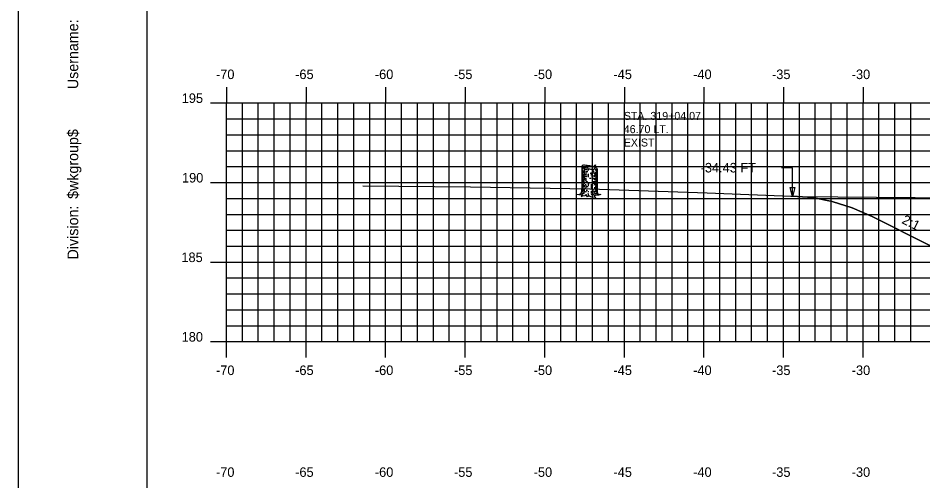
# Model space of a CAD drawing. Extents: x 1139428 to 1139598, y 608981 to 609091.
# Drawn here: x 1139428.4 to 1139485.2, y 609011.6 to 609040.7 of the extents above; entities that cross this region are included whole.
import ezdxf

# ---------------------------------------------------------------- set-up
doc = ezdxf.new("R2010")
doc.units = 0
for name, color, linetype in [('ANNOTATION', 7, 'Continuous'), ('BORDER', 7, 'Continuous'), ('D_Roadway_SlopeLines', 7, 'Continuous'), ('D_Text_Monospaced', 7, 'Continuous'), ('D_Text_Standard', 7, 'Continuous'), ('H_V ANNOTATION', 7, 'Continuous'), ('MAJOR', 7, 'Continuous'), ('MINOR', 7, 'Continuous'), ('PLOT BOUNDARY', 7, 'Continuous'), ('S_Roadway_Centerline', 7, 'Continuous'), ('S_Trees_Decid_NonPay', 7, 'Continuous')]:
    doc.layers.add(name, color=color, linetype=linetype)

msp = doc.modelspace()

# ---------------------------------------------------------------- linework, layer by layer
msp.add_lwpolyline([(1139477.03, 609029.476), (1139478.28, 609029.383), (1139479.53, 609029.138), (1139480.78, 609028.741), (1139482.03, 609028.192), (1139485.737, 609026.338), (1139488.737, 609027.338), (1139496.461, 609029.913), (1139496.462, 609029.913), (1139500.462, 609030.073), (1139511.462, 609030.293), (1139522.462, 609030.073), (1139526.462, 609029.913), (1139534.185, 609027.338), (1139537.185, 609026.338), (1139537.772, 609026.632), (1139539.022, 609027.171), (1139540.272, 609027.537), (1139541.522, 609027.732), (1139542.772, 609027.754)])
at = {"layer": 'BORDER'}
msp.add_lwpolyline([(1139436.462, 608984.335), (1139596.462, 608984.335), (1139596.462, 609089.335), (1139436.462, 609089.335)], close=True, dxfattribs=at)
at = {"layer": 'D_Roadway_SlopeLines'}
msp.add_lwpolyline([(1139485.737, 609026.338), (1139482.03, 609028.192), (1139480.78, 609028.741), (1139479.53, 609029.138), (1139478.28, 609029.383), (1139477.03, 609029.476)], dxfattribs=at)
at = {"layer": 'D_Text_Standard'}
msp.add_lwpolyline([(1139477.03, 609029.442), (1139477.027, 609031.267), (1139476.347, 609031.267)], dxfattribs=at)
msp.add_lwpolyline([(1139477.03, 609029.442), (1139476.884, 609030.024), (1139477.175, 609030.024)], close=True, dxfattribs=at)
at = {"layer": 'MAJOR'}
for p, q in [((1139441.462, 609036.337), (1139441.462, 609035.335)), ((1139446.462, 609036.337), (1139446.462, 609035.335)), ((1139451.462, 609036.337), (1139451.462, 609035.335)), ((1139456.462, 609036.337), (1139456.462, 609035.335)), ((1139461.462, 609036.337), (1139461.462, 609035.335)), ((1139466.462, 609036.337), (1139466.462, 609035.335)), ((1139471.462, 609036.337), (1139471.462, 609035.335)), ((1139476.462, 609036.337), (1139476.462, 609035.335)), ((1139481.462, 609036.337), (1139481.462, 609035.335)), ((1139440.46, 609035.335), (1139441.462, 609035.335)), ((1139441.462, 609035.335), (1139581.462, 609035.335)), ((1139441.462, 609020.335), (1139441.462, 609035.335)), ((1139441.462, 609020.335), (1139441.462, 609035.335)), ((1139441.462, 609035.335), (1139581.462, 609035.335)), ((1139446.462, 609020.335), (1139446.462, 609035.335)), ((1139451.462, 609020.335), (1139451.462, 609035.335)), ((1139456.462, 609020.335), (1139456.462, 609035.335)), ((1139461.462, 609020.335), (1139461.462, 609035.335)), ((1139466.462, 609020.335), (1139466.462, 609035.335)), ((1139471.462, 609020.335), (1139471.462, 609035.335)), ((1139476.462, 609020.335), (1139476.462, 609035.335)), ((1139481.462, 609020.335), (1139481.462, 609035.335)), ((1139440.46, 609030.335), (1139441.462, 609030.335)), ((1139441.462, 609030.335), (1139581.462, 609030.335)), ((1139440.46, 609025.335), (1139441.462, 609025.335)), ((1139441.462, 609025.335), (1139581.462, 609025.335)), ((1139440.46, 609020.335), (1139441.462, 609020.335)), ((1139441.462, 609020.335), (1139581.462, 609020.335)), ((1139441.462, 609020.335), (1139581.462, 609020.335)), ((1139441.462, 609019.333), (1139441.462, 609020.335)), ((1139446.462, 609019.333), (1139446.462, 609020.335)), ((1139451.462, 609019.333), (1139451.462, 609020.335)), ((1139456.462, 609019.333), (1139456.462, 609020.335)), ((1139461.462, 609019.333), (1139461.462, 609020.335)), ((1139466.462, 609019.333), (1139466.462, 609020.335)), ((1139471.462, 609019.333), (1139471.462, 609020.335)), ((1139476.462, 609019.333), (1139476.462, 609020.335)), ((1139481.462, 609019.333), (1139481.462, 609020.335))]:
    msp.add_line(p, q, dxfattribs=at)
at = {"layer": 'MINOR'}
for p, q in [((1139442.462, 609020.335), (1139442.462, 609035.335)), ((1139443.462, 609020.335), (1139443.462, 609035.335)), ((1139444.462, 609020.335), (1139444.462, 609035.335)), ((1139445.462, 609020.335), (1139445.462, 609035.335)), ((1139447.462, 609020.335), (1139447.462, 609035.335)), ((1139448.462, 609020.335), (1139448.462, 609035.335)), ((1139449.462, 609020.335), (1139449.462, 609035.335)), ((1139450.462, 609020.335), (1139450.462, 609035.335)), ((1139452.462, 609020.335), (1139452.462, 609035.335)), ((1139453.462, 609020.335), (1139453.462, 609035.335)), ((1139454.462, 609020.335), (1139454.462, 609035.335)), ((1139455.462, 609020.335), (1139455.462, 609035.335)), ((1139457.462, 609020.335), (1139457.462, 609035.335)), ((1139458.462, 609020.335), (1139458.462, 609035.335)), ((1139459.462, 609020.335), (1139459.462, 609035.335)), ((1139460.462, 609020.335), (1139460.462, 609035.335)), ((1139462.462, 609020.335), (1139462.462, 609035.335)), ((1139463.462, 609020.335), (1139463.462, 609035.335)), ((1139464.462, 609020.335), (1139464.462, 609035.335)), ((1139465.462, 609020.335), (1139465.462, 609035.335)), ((1139467.462, 609020.335), (1139467.462, 609035.335)), ((1139468.462, 609020.335), (1139468.462, 609035.335)), ((1139469.462, 609020.335), (1139469.462, 609035.335)), ((1139470.462, 609020.335), (1139470.462, 609035.335)), ((1139472.462, 609020.335), (1139472.462, 609035.335)), ((1139473.462, 609020.335), (1139473.462, 609035.335)), ((1139474.462, 609020.335), (1139474.462, 609035.335)), ((1139475.462, 609020.335), (1139475.462, 609035.335)), ((1139477.462, 609020.335), (1139477.462, 609035.335)), ((1139478.462, 609020.335), (1139478.462, 609035.335)), ((1139479.462, 609020.335), (1139479.462, 609035.335)), ((1139480.462, 609020.335), (1139480.462, 609035.335)), ((1139482.462, 609020.335), (1139482.462, 609035.335)), ((1139483.462, 609020.335), (1139483.462, 609035.335)), ((1139484.462, 609020.335), (1139484.462, 609035.335)), ((1139441.462, 609034.335), (1139581.462, 609034.335)), ((1139441.462, 609034.335), (1139442.464, 609034.335)), ((1139441.462, 609033.335), (1139581.462, 609033.335)), ((1139441.462, 609033.335), (1139442.464, 609033.335)), ((1139441.462, 609032.335), (1139581.462, 609032.335)), ((1139441.462, 609032.335), (1139442.464, 609032.335)), ((1139441.462, 609031.335), (1139581.462, 609031.335)), ((1139441.462, 609031.335), (1139442.464, 609031.335)), ((1139441.462, 609029.335), (1139581.462, 609029.335)), ((1139441.462, 609029.335), (1139442.464, 609029.335)), ((1139441.462, 609028.335), (1139581.462, 609028.335)), ((1139441.462, 609028.335), (1139442.464, 609028.335)), ((1139441.462, 609027.335), (1139581.462, 609027.335)), ((1139441.462, 609027.335), (1139442.464, 609027.335)), ((1139441.462, 609026.335), (1139581.462, 609026.335)), ((1139441.462, 609026.335), (1139442.464, 609026.335)), ((1139441.462, 609024.335), (1139581.462, 609024.335)), ((1139441.462, 609024.335), (1139442.464, 609024.335)), ((1139441.462, 609023.335), (1139581.462, 609023.335)), ((1139441.462, 609023.335), (1139442.464, 609023.335)), ((1139441.462, 609022.335), (1139581.462, 609022.335)), ((1139441.462, 609022.335), (1139442.464, 609022.335)), ((1139441.462, 609021.335), (1139581.462, 609021.335)), ((1139441.462, 609021.335), (1139442.464, 609021.335))]:
    msp.add_line(p, q, dxfattribs=at)
at = {"layer": 'PLOT BOUNDARY'}
msp.add_lwpolyline([(1139428.369, 608981.276), (1139598.369, 608981.276), (1139598.369, 609091.276), (1139428.369, 609091.276)], close=True, dxfattribs=at)
at = {"layer": 'S_Roadway_Centerline'}
msp.add_lwpolyline([(1139450.03, 609030.117), (1139456.785, 609030.069), (1139464.298, 609029.937), (1139471.664, 609029.689), (1139477.443, 609029.46), (1139487.16, 609029.377)], dxfattribs=at)
at = {"layer": 'S_Trees_Decid_NonPay'}
for p, q in [((1139463.86, 609031.322), (1139463.86, 609031.227)), ((1139463.86, 609031.001), (1139463.86, 609030.918)), ((1139463.86, 609030.849), (1139463.86, 609030.597)), ((1139463.928, 609031.235), (1139463.928, 609030.935)), ((1139463.928, 609030.906), (1139463.928, 609030.775)), ((1139464.047, 609031.252), (1139464.047, 609031.104)), ((1139464.047, 609031.056), (1139464.047, 609030.888)), ((1139464.194, 609031.206), (1139464.194, 609031.099)), ((1139464.194, 609030.871), (1139464.194, 609030.784)), ((1139464.374, 609030.97), (1139464.374, 609030.77)), ((1139464.491, 609031.154), (1139464.491, 609031.075)), ((1139464.491, 609030.989), (1139464.491, 609030.904)), ((1139464.491, 609030.793), (1139464.491, 609030.692)), ((1139464.578, 609030.97), (1139464.578, 609030.884)), ((1139464.578, 609030.813), (1139464.578, 609030.692)), ((1139464.649, 609031.143), (1139464.649, 609031.092)), ((1139464.649, 609030.989), (1139464.649, 609030.906)), ((1139464.649, 609030.871), (1139464.649, 609030.797)), ((1139464.691, 609031.149), (1139464.691, 609030.931)), ((1139464.691, 609030.862), (1139464.691, 609030.71)), ((1139464.718, 609031.078), (1139464.718, 609030.996)), ((1139464.718, 609030.927), (1139464.718, 609030.797)), ((1139464.718, 609030.775), (1139464.718, 609030.593)), ((1139463.86, 609030.515), (1139463.86, 609030.284)), ((1139463.86, 609030.214), (1139463.86, 609030.054)), ((1139463.928, 609030.741), (1139463.928, 609030.46)), ((1139463.928, 609030.389), (1139463.928, 609030.245)), ((1139464.047, 609030.581), (1139464.047, 609030.433)), ((1139464.194, 609030.75), (1139464.194, 609030.68)), ((1139464.194, 609030.346), (1139464.194, 609030.124)), ((1139464.374, 609030.233), (1139464.374, 609030.046)), ((1139464.491, 609030.607), (1139464.491, 609030.531)), ((1139464.491, 609030.346), (1139464.491, 609030.249)), ((1139464.578, 609030.617), (1139464.578, 609030.502)), ((1139464.578, 609030.441), (1139464.578, 609030.359)), ((1139464.578, 609030.272), (1139464.578, 609030.175)), ((1139464.649, 609030.77), (1139464.649, 609030.71)), ((1139464.649, 609030.657), (1139464.649, 609030.476)), ((1139464.649, 609030.445), (1139464.649, 609030.363)), ((1139464.649, 609030.309), (1139464.649, 609030.138)), ((1139464.691, 609030.605), (1139464.691, 609030.527)), ((1139464.691, 609030.5), (1139464.691, 609030.393)), ((1139464.691, 609030.359), (1139464.691, 609030.258)), ((1139464.691, 609030.232), (1139464.691, 609030.05)), ((1139464.718, 609030.546), (1139464.718, 609030.299)), ((1139464.718, 609030.28), (1139464.718, 609030.185)), ((1139463.86, 609030.037), (1139463.86, 609029.932)), ((1139463.86, 609029.895), (1139463.86, 609029.771)), ((1139463.928, 609029.691), (1139463.886, 609029.595)), ((1139463.928, 609030.175), (1139463.928, 609030.033)), ((1139463.928, 609029.932), (1139463.928, 609029.751)), ((1139464.047, 609030.163), (1139464.047, 609030.01)), ((1139464.047, 609029.798), (1139464.047, 609029.72)), ((1139464.194, 609029.79), (1139464.194, 609029.724)), ((1139464.234, 609029.504), (1139464.199, 609029.65)), ((1139464.374, 609030.015), (1139464.374, 609029.962)), ((1139464.374, 609029.786), (1139464.374, 609029.695)), ((1139464.491, 609029.924), (1139464.491, 609029.7)), ((1139464.578, 609030.046), (1139464.578, 609029.947)), ((1139464.578, 609029.817), (1139464.578, 609029.759)), ((1139464.649, 609030.105), (1139464.649, 609029.825)), ((1139464.649, 609029.773), (1139464.649, 609029.747)), ((1139464.689, 609029.708), (1139464.724, 609029.657)), ((1139464.691, 609029.947), (1139464.691, 609029.755)), ((1139464.718, 609029.834), (1139464.718, 609029.76)), ((1139464.72, 609030.132), (1139464.719, 609029.872)), ((1139464.771, 609029.586), (1139464.704, 609029.617))]:
    msp.add_line(p, q, dxfattribs=at)
for points in [[(1139464.76, 609031.186), (1139464.76, 609029.774), (1139464.782, 609029.626), (1139464.985, 609029.582), (1139464.846, 609029.547), (1139464.627, 609029.529), (1139464.558, 609029.485), (1139464.679, 609029.397), (1139464.348, 609029.44), (1139464.234, 609029.504), (1139464.142, 609029.444), (1139464.086, 609029.523), (1139464.094, 609029.559), (1139464.033, 609029.561), (1139463.981, 609029.504), (1139463.748, 609029.452), (1139463.876, 609029.541), (1139463.744, 609029.543), (1139463.435, 609029.58), (1139463.674, 609029.611), (1139463.752, 609029.669), (1139463.791, 609029.79), (1139463.808, 609030.144), (1139463.808, 609031.378)], [(1139464.172, 609031.212), (1139464.164, 609031.279), (1139464.14, 609031.283), (1139464.131, 609031.318), (1139464.1, 609031.304), (1139464.086, 609031.318), (1139464.061, 609031.295), (1139464.039, 609031.304), (1139464.026, 609031.353), (1139464.018, 609031.309), (1139463.987, 609031.318), (1139463.984, 609031.267)], [(1139464.664, 609031.267), (1139464.661, 609031.361), (1139464.646, 609031.334), (1139464.646, 609031.456), (1139464.625, 609031.392), (1139464.611, 609031.425), (1139464.594, 609031.369), (1139464.578, 609031.386), (1139464.559, 609031.378), (1139464.54, 609031.311)], [(1139464.642, 609031.143), (1139464.625, 609031.204), (1139464.603, 609031.193), (1139464.572, 609031.227), (1139464.539, 609031.149)], [(1139463.857, 609029.729), (1139463.849, 609029.652), (1139463.771, 609029.603)], [(1139464.382, 609029.646), (1139464.382, 609029.609), (1139464.434, 609029.578), (1139464.451, 609029.529)], [(1139464.494, 609029.652), (1139464.5, 609029.582), (1139464.563, 609029.57)], [(1139464.642, 609029.617), (1139464.598, 609029.652), (1139464.59, 609029.7)], [(1139464.72, 609029.634), (1139464.642, 609029.617), (1139464.625, 609029.574)]]:
    msp.add_lwpolyline(points, dxfattribs=at)
for centre, radius, start, end in [((1139463.826, 609031.378), 0.0179, 168.1723, 184.2278), ((1139463.826, 609031.378), 0.0179, 152.1168, 168.1723), ((1139463.832, 609031.378), 0.0237, 184.2278, 198.1723), ((1139463.842, 609031.381), 0.0336, 198.1723, 216.9486), ((1139463.832, 609031.375), 0.0237, 138.1723, 152.1168), ((1139463.839, 609031.368), 0.0336, 119.396, 138.1723), ((1139463.889, 609031.417), 0.0935, 216.9486, 228.1723), ((1139463.868, 609031.316), 0.0935, 108.1723, 119.396), ((1139464.042, 609031.587), 0.322, 228.1723, 250.2902), ((1139463.939, 609031.099), 0.322, 86.0543, 108.1723), ((1139463.789, 609028.919), 2.507, 78.1723, 86.0543), ((1139463.789, 609028.919), 2.507, 70.2902, 78.1723), ((1139463.827, 609031.23), 0.0191, 163.9485, 180), ((1139463.827, 609031.23), 0.0191, 180, 196.0515), ((1139463.833, 609031.232), 0.0252, 196.0515, 210), ((1139463.827, 609031.016), 0.0191, 163.9485, 180), ((1139463.827, 609031.016), 0.0191, 180, 196.0515), ((1139463.833, 609031.018), 0.0252, 196.0515, 210), ((1139463.827, 609030.913), 0.0191, 163.9485, 180), ((1139463.827, 609030.913), 0.0191, 180, 196.0515), ((1139463.833, 609030.915), 0.0252, 196.0515, 210), ((1139463.842, 609031.237), 0.0356, 210, 228.7494), ((1139463.842, 609031.023), 0.0356, 210, 228.7494), ((1139463.842, 609030.92), 0.0356, 210, 228.7494), ((1139463.883, 609031.284), 0.0984, 228.7494, 240), ((1139463.883, 609031.07), 0.0984, 228.7494, 240), ((1139463.883, 609030.967), 0.0984, 228.7494, 240), ((1139463.997, 609031.482), 0.326, 240, 248.3243), ((1139463.997, 609031.267), 0.326, 240, 243.5719), ((1139463.997, 609031.165), 0.326, 240, 243.243), ((1139463.997, 609031.368), 0.326, 240.9099, 257.8036), ((1139463.997, 609031.267), 0.326, 250.4167, 261.8968), ((1139463.997, 609031.165), 0.326, 251.6831, 257.8036), ((1139463.997, 609031.482), 0.326, 257.8036, 261.8968), ((1139464.779, 609033.644), 2.507, 250.2902, 251.5281), ((1139464.283, 609033.492), 2.356, 261.8968, 263.2799), ((1139464.283, 609033.278), 2.356, 261.8968, 262.5519), ((1139464.283, 609033.175), 2.356, 263.3413, 264.9946), ((1139464.283, 609033.378), 2.356, 264.242, 267.3673), ((1139464.283, 609033.492), 2.356, 265.24, 267.8386), ((1139464.283, 609033.175), 2.356, 266.5036, 267.8386), ((1139464.779, 609033.644), 2.507, 255.9987, 258.1723), ((1139464.779, 609033.644), 2.507, 258.1723, 264.5013), ((1139464.283, 609033.278), 2.356, 270.8119, 272.1981), ((1139464.283, 609033.175), 2.356, 272.1981, 273.9741), ((1139464.283, 609033.378), 2.356, 273.1481, 276.7734), ((1139464.283, 609033.278), 2.356, 275.0647, 278.1032), ((1139464.283, 609033.175), 2.356, 277.3838, 278.1032), ((1139464.569, 609031.267), 0.326, 278.1032, 279.0854), ((1139464.569, 609031.165), 0.326, 278.1032, 284.0382), ((1139464.526, 609030.976), 0.322, 48.1723, 70.2902), ((1139464.628, 609031.465), 0.322, 272.4479, 288.1723), ((1139464.569, 609031.368), 0.326, 291.9506, 300), ((1139464.569, 609031.267), 0.326, 291.9506, 300), ((1139464.569, 609031.06), 0.326, 291.9506, 300), ((1139464.7, 609031.248), 0.0935, 288.1723, 299.396), ((1139464.683, 609031.171), 0.0984, 300, 311.2506), ((1139464.683, 609031.07), 0.0984, 300, 311.2506), ((1139464.683, 609030.862), 0.0984, 300, 311.2506), ((1139464.678, 609031.147), 0.0935, 36.9486, 48.1723), ((1139464.729, 609031.195), 0.0336, 299.396, 318.1723), ((1139464.725, 609031.124), 0.0356, 311.2506, 330), ((1139464.725, 609031.023), 0.0356, 311.2506, 330), ((1139464.725, 609030.815), 0.0356, 311.2506, 330), ((1139464.726, 609031.183), 0.0336, 18.1723, 36.9486), ((1139464.736, 609031.189), 0.0237, 318.1723, 332.1168), ((1139464.734, 609031.119), 0.0252, 330, 343.9485), ((1139464.734, 609031.018), 0.0252, 330, 343.9485), ((1139464.734, 609030.81), 0.0252, 330, 343.9485), ((1139464.741, 609031.186), 0.0179, 332.1168, 348.1723), ((1139464.736, 609031.186), 0.0237, 4.2278, 18.1723), ((1139464.74, 609031.117), 0.0191, 360, 6.1128), ((1139464.74, 609031.117), 0.0191, 343.9485, 360), ((1139464.74, 609031.016), 0.0191, 360, 6.1128), ((1139464.74, 609031.016), 0.0191, 343.9485, 360), ((1139464.74, 609030.913), 0.0191, 360, 6.1128), ((1139464.74, 609030.913), 0.0191, 343.9485, 360), ((1139464.74, 609030.808), 0.0191, 360, 6.1128), ((1139464.74, 609030.808), 0.0191, 343.9485, 360), ((1139464.741, 609031.186), 0.0179, 348.1723, 4.2278), ((1139463.824, 609030.479), 0.0191, 163.9485, 180), ((1139463.827, 609030.693), 0.0191, 163.9485, 180), ((1139463.827, 609030.693), 0.0191, 180, 196.0515), ((1139463.833, 609030.695), 0.0252, 196.0515, 210), ((1139463.828, 609030.579), 0.0191, 163.9485, 180), ((1139463.828, 609030.579), 0.0191, 180, 196.0515), ((1139463.827, 609030.374), 0.0191, 163.9485, 180), ((1139463.827, 609030.374), 0.0191, 180, 196.0515), ((1139463.833, 609030.375), 0.0252, 196.0515, 210), ((1139463.833, 609030.58), 0.0252, 196.0515, 210), ((1139463.842, 609030.7), 0.0356, 210, 228.7494), ((1139463.842, 609030.381), 0.0356, 210, 228.7494), ((1139463.842, 609030.586), 0.0356, 210, 228.7494), ((1139463.883, 609030.747), 0.0984, 228.7494, 240), ((1139463.883, 609030.428), 0.0984, 228.7494, 240), ((1139463.884, 609030.633), 0.0984, 228.7494, 240), ((1139463.995, 609030.73), 0.326, 240, 256.9079), ((1139463.997, 609030.944), 0.326, 240, 245.1545), ((1139463.997, 609030.625), 0.326, 240, 245.1545), ((1139463.998, 609030.83), 0.326, 240, 247.8656), ((1139463.997, 609030.535), 0.326, 241.939, 253.9183), ((1139463.997, 609031.06), 0.326, 245.1545, 257.8036), ((1139463.998, 609030.83), 0.326, 257.6699, 261.8968), ((1139464.284, 609032.84), 2.356, 261.8968, 262.8615), ((1139464.283, 609032.545), 2.356, 262.5843, 264.4865), ((1139464.283, 609032.955), 2.356, 262.6588, 264.7911), ((1139464.283, 609033.07), 2.356, 263.2682, 265.6362), ((1139464.281, 609032.74), 2.356, 264.3443, 266.8529), ((1139464.283, 609032.635), 2.356, 267.8386, 269.0054), ((1139464.283, 609032.955), 2.356, 269.5578, 270), ((1139464.283, 609032.955), 2.356, 270, 272.414), ((1139464.283, 609033.07), 2.356, 273.0067, 275.0647), ((1139464.281, 609032.74), 2.356, 274.9734, 277.2455), ((1139464.283, 609032.955), 2.356, 275.0647, 277.1868), ((1139464.283, 609032.635), 2.356, 275.0647, 276.428), ((1139464.283, 609033.07), 2.356, 277.1868, 278.1032), ((1139464.569, 609031.06), 0.326, 278.1032, 284.0382), ((1139464.569, 609030.944), 0.326, 284.0382, 300), ((1139464.57, 609030.83), 0.326, 283.9036, 291.8098), ((1139464.569, 609030.625), 0.326, 284.0382, 291.9506), ((1139464.567, 609030.73), 0.326, 292.4049, 300), ((1139464.57, 609030.83), 0.326, 297.0058, 300), ((1139464.569, 609030.625), 0.326, 297.1525, 300), ((1139464.681, 609030.533), 0.0984, 300, 311.2506), ((1139464.683, 609030.747), 0.0984, 300, 311.2506), ((1139464.683, 609030.428), 0.0984, 300, 311.2506), ((1139464.684, 609030.633), 0.0984, 300, 311.2506), ((1139464.722, 609030.485), 0.0356, 311.2506, 330), ((1139464.725, 609030.7), 0.0356, 311.2506, 330), ((1139464.725, 609030.381), 0.0356, 311.2506, 330), ((1139464.725, 609030.586), 0.0356, 311.2506, 330), ((1139464.731, 609030.48), 0.0252, 330, 343.9485), ((1139464.734, 609030.695), 0.0252, 330, 343.9485), ((1139464.737, 609030.479), 0.0191, 343.9485, 360), ((1139464.734, 609030.375), 0.0252, 330, 343.9485), ((1139464.734, 609030.58), 0.0252, 330, 343.9485), ((1139464.737, 609030.479), 0.0191, 0, 6.1128), ((1139464.74, 609030.693), 0.0191, 360, 6.1128), ((1139464.74, 609030.693), 0.0191, 343.9485, 360), ((1139464.74, 609030.374), 0.0191, 360, 6.1128), ((1139464.74, 609030.374), 0.0191, 343.9485, 360), ((1139464.74, 609030.283), 0.0191, 360, 6.1128), ((1139464.74, 609030.579), 0.0191, 0, 6.1128), ((1139464.74, 609030.579), 0.0191, 343.9485, 360), ((1139463.812, 609029.834), 0.0191, 163.9485, 180), ((1139463.812, 609029.834), 0.0191, 180, 196.0515), ((1139463.818, 609029.836), 0.0252, 196.0515, 210), ((1139463.827, 609029.841), 0.0356, 210, 228.7494), ((1139463.818, 609029.944), 0.0191, 163.9485, 180), ((1139463.818, 609029.944), 0.0191, 180, 196.0515), ((1139463.824, 609029.946), 0.0252, 196.0515, 210), ((1139463.833, 609029.951), 0.0356, 210, 228.7494), ((1139463.823, 609030.055), 0.0191, 163.9485, 180), ((1139463.823, 609030.055), 0.0191, 180, 196.0515), ((1139463.829, 609030.056), 0.0252, 196.0515, 210), ((1139463.869, 609029.888), 0.0984, 228.7494, 240), ((1139463.838, 609030.062), 0.0356, 210, 228.7494), ((1139463.874, 609029.998), 0.0984, 228.7494, 240), ((1139463.879, 609030.109), 0.0984, 228.7494, 240), ((1139463.983, 609030.085), 0.326, 240, 247.9161), ((1139463.988, 609030.195), 0.326, 240, 241.9097), ((1139463.993, 609030.306), 0.326, 240, 245.9375), ((1139463.983, 609030.085), 0.326, 260.3834, 261.8968), ((1139464.269, 609032.095), 2.356, 261.8968, 263.5333), ((1139464.279, 609032.316), 2.356, 262.2226, 264.4852), ((1139464.283, 609032.431), 2.356, 264.242, 267.469), ((1139464.274, 609032.205), 2.356, 264.9089, 266.8158), ((1139464.283, 609032.545), 2.356, 272.1981, 275.2726), ((1139464.274, 609032.205), 2.356, 274.1864, 275.2829), ((1139464.269, 609032.095), 2.356, 274.5551, 275.4167), ((1139464.279, 609032.316), 2.356, 277.2863, 278.1032), ((1139464.269, 609032.095), 2.356, 277.5403, 278.1032), ((1139464.555, 609030.085), 0.326, 278.1032, 294.7094), ((1139464.565, 609030.306), 0.326, 278.1032, 284.7741), ((1139464.569, 609030.421), 0.326, 284.0382, 291.9506), ((1139464.56, 609030.195), 0.326, 293.6544, 300), ((1139464.669, 609029.888), 0.0984, 300, 311.2506), ((1139464.679, 609030.109), 0.0984, 300, 311.2506), ((1139464.71, 609029.841), 0.0356, 311.2506, 330), ((1139464.719, 609029.836), 0.0252, 330, 343.9485), ((1139464.725, 609029.834), 0.0191, 343.9485, 360), ((1139464.721, 609030.062), 0.0356, 311.2506, 330), ((1139464.725, 609029.834), 0.0191, 0, 6.1128), ((1139464.73, 609030.056), 0.0252, 330, 343.9485), ((1139464.735, 609030.055), 0.0191, 360, 6.1128), ((1139464.735, 609030.055), 0.0191, 343.9485, 360)]:
    msp.add_arc(centre, radius, start, end, dxfattribs=at)

# ---------------------------------------------------------------- texts
at = {"layer": 'ANNOTATION'}
msp.add_text('2:1', height=0.6, rotation=333.4349, dxfattribs=at).set_placement((1139483.851, 609027.8))
at = {"layer": 'BORDER'}
for s, p in [('Username:', (1139432.147, 609036.203)), ('$wkgroup$', (1139432.147, 609029.305)), ('Division:', (1139432.147, 609025.501))]:
    msp.add_text(s, height=0.6696, rotation=90, dxfattribs=at).set_placement(p)
at = {"layer": 'D_Text_Monospaced'}
for s, height, p in [('STA. 319+04.07', 0.49998, (1139466.426, 609034.272)), ('46.70 LT.', 0.5, (1139466.426, 609033.438)), ('EXIST. ', 0.5, (1139466.426, 609032.598))]:
    msp.add_text(s, height=height, dxfattribs=at).set_placement(p)
at = {"layer": 'D_Text_Standard'}
msp.add_text('-34.43 FT', height=0.6, dxfattribs=at).set_placement((1139471.257, 609030.967))
at = {"layer": 'H_V ANNOTATION'}
for s, p in [('-70', (1139440.803, 609036.835)), ('-65', (1139445.779, 609036.835)), ('-60', (1139450.787, 609036.835)), ('-55', (1139455.758, 609036.835)), ('-50', (1139460.766, 609036.835)), ('-45', (1139465.779, 609036.835)), ('-40', (1139470.787, 609036.835)), ('-35', (1139475.742, 609036.835)), ('-30', (1139480.75, 609036.835)), ('195', (1139438.651, 609035.335)), ('190', (1139438.667, 609030.335)), ('185', (1139438.629, 609025.335)), ('180', (1139438.645, 609020.335)), ('-70', (1139440.803, 609018.235)), ('-65', (1139445.779, 609018.235)), ('-60', (1139450.787, 609018.235)), ('-55', (1139455.758, 609018.235)), ('-50', (1139460.766, 609018.235)), ('-45', (1139465.779, 609018.235)), ('-40', (1139470.787, 609018.235)), ('-35', (1139475.742, 609018.235)), ('-30', (1139480.75, 609018.235)), ('-70', (1139440.803, 609011.835)), ('-65', (1139445.779, 609011.835)), ('-60', (1139450.787, 609011.835)), ('-55', (1139455.758, 609011.835)), ('-50', (1139460.766, 609011.835)), ('-45', (1139465.779, 609011.835)), ('-40', (1139470.787, 609011.835)), ('-35', (1139475.742, 609011.835)), ('-30', (1139480.75, 609011.835))]:
    msp.add_text(s, height=0.6, dxfattribs=at).set_placement(p)
at = {"layer": 'MAJOR'}
msp.add_text('-', height=0.006, dxfattribs=at).set_placement((1139441.457, 609020.335))

doc.saveas('drawing.dxf')
